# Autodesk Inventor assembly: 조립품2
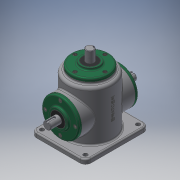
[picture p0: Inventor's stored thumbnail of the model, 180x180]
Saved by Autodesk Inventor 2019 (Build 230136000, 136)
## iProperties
Created: 2020-12
Part Number: 조립품2
Material: 일반
Document SubType Name: Assembly
Designer: jun-1-15
Author: jun-1-15
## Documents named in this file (16)
- C:\Users\jun-1-15\Desktop\701207V1002\조립품2.iam
- C:\Users\jun-1-15\Desktop\701207V1002\본체.ipt
- C:\Users\jun-1-15\Desktop\701207V1002\메인 베벨기어.ipt
- C:\Users\jun-1-15\Desktop\701207V1002\메인 축.ipt
- 메인 축.ipt
- C:\Users\jun-1-15\Desktop\701207V1002\베어링 6203.ipt
- C:\Users\jun-1-15\Desktop\701207V1002\볼트 M4.ipt
- 볼트 M4.ipt
- C:\Users\jun-1-15\Desktop\701207V1002\서브 베벨기어.ipt
- C:\Users\jun-1-15\Desktop\701207V1002\서브 축.ipt
- 서브 축.ipt
- C:\Users\jun-1-15\Desktop\701207V1002\오일 실.ipt
- 오일 실.ipt
- C:\Users\jun-1-15\Desktop\701207V1002\커버.ipt
- C:\Users\jun-1-15\Desktop\701207V1002\키 4x4.ipt
- C:\Users\jun-1-15\Desktop\701207V1002\키 5x5.ipt
